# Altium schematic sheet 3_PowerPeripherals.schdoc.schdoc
size 309 x 223 mm; Symbol: Artery_A4; Device: Artery_A4; @Page Count: 4; @Create Date: 2024-01-02; @Page Name: PowerPeripherals; @Project Name: AT-START-L021; @Update Date: 2024-02-21; @Schematic Name: AT-START-L021_V1.0; @Page No: 3; Company: Artery Technology; Drawed: SD; Version: 1.0; Page Size: A4
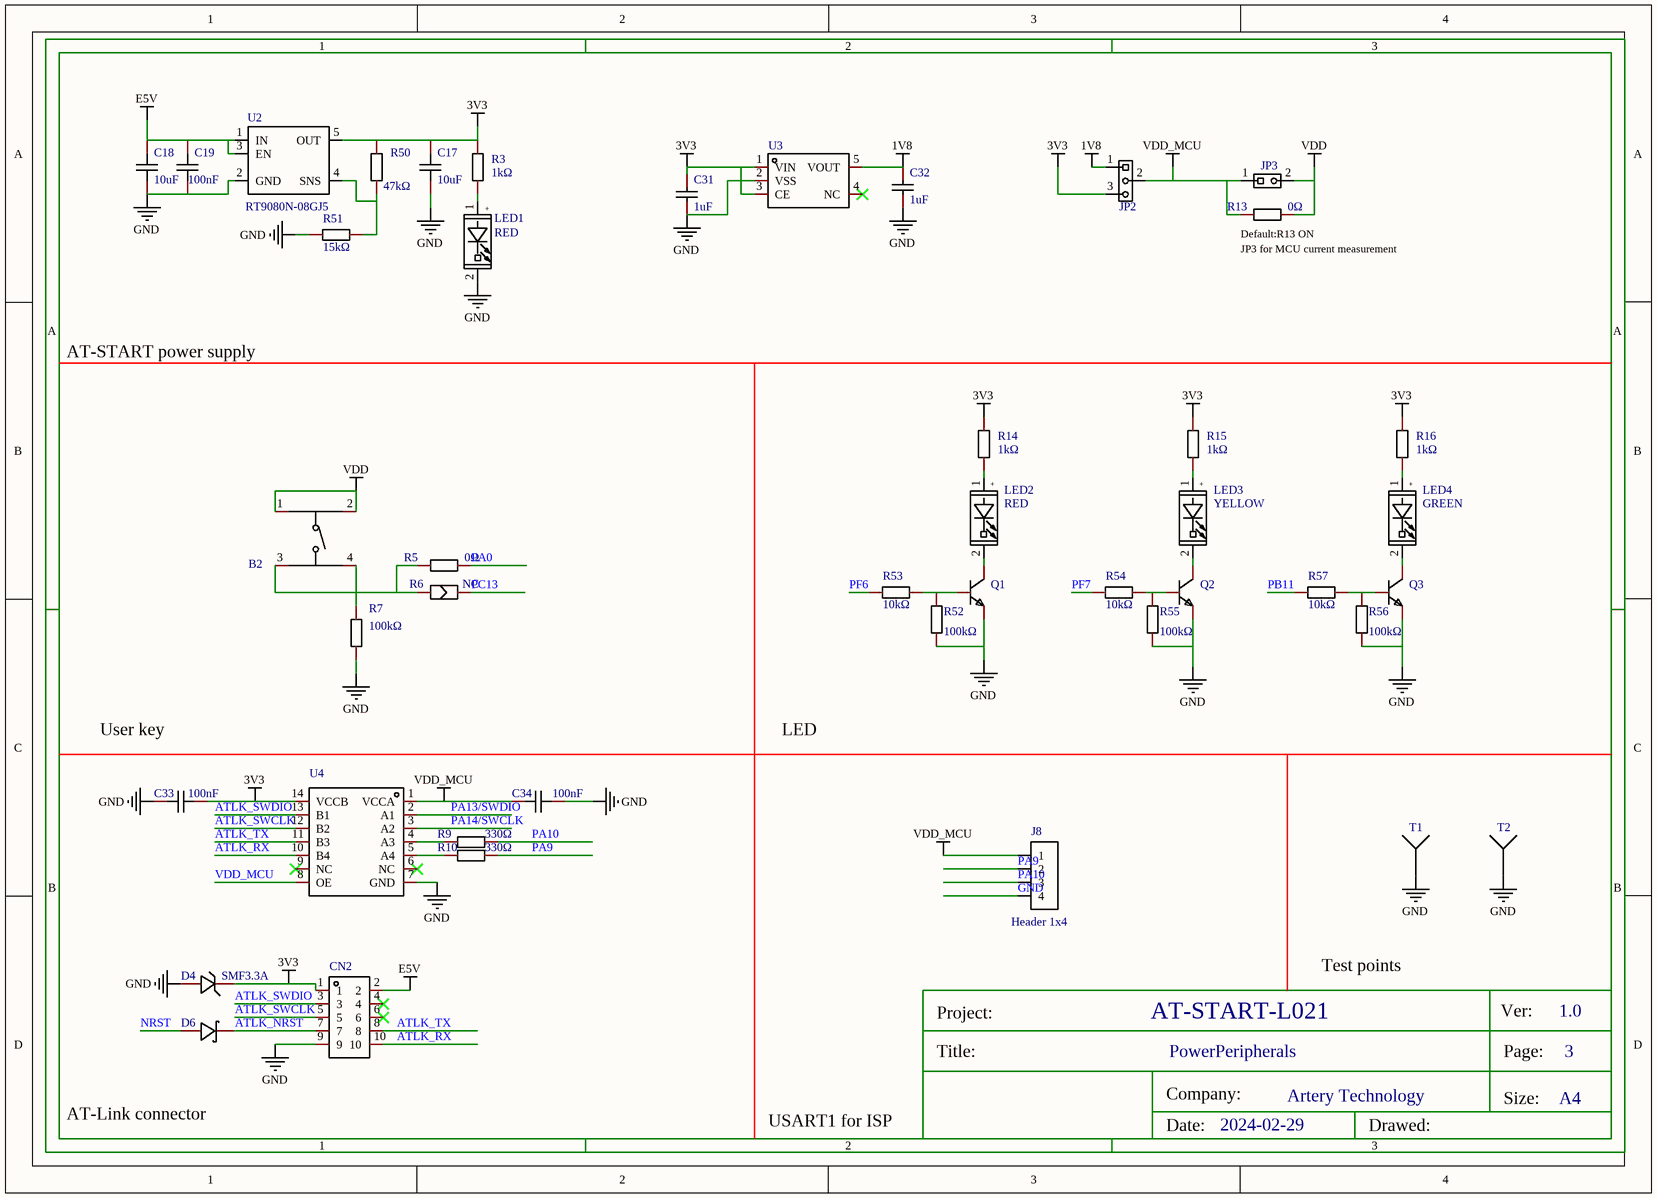
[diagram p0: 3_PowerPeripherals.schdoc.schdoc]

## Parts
B2  蓝色  [BUTTON_SMT_6*6*5]  (value not drawn)
C17  value 10uF  [C0603]  (hidden comment: CL10A106KP8NNNC)
C18  value 10uF  [C0603]  (hidden comment: CL10A106KP8NNNC)
C19  value 100nF  [C0603]  (hidden comment: CC0603KRX7R9BB104)
C31  value 1uF  [C0603]  (hidden comment: CL10A105KB8NNNC)
C32  value 1uF  [C0603]  (hidden comment: CL10A105KB8NNNC)
C33  value 100nF  [C0603]  (hidden comment: CC0603KRX7R9BB104)
C34  value 100nF  [C0603]  (hidden comment: CC0603KRX7R9BB104)
CN2  Z-21310110021001  [HDR-TH_10P-P2.54-V-M-R2-C5-S2.54]  (value not drawn)
D4  SMF3.3A  [SOD-123_L2.8-W1.8-LS3.7-RD]
D6  LRB521S-40T1G  [SOD-523_L1.2-W0.8-LS1.6-RD]  (value not drawn)
J8  Header 1x4  [HDR1X4]
JP2  Header 1x3  [HEADER 1X3]  (value not drawn)
JP3  NC(Header 1x2)  [HDR1X2]  (value not drawn)
LED1  RED  [LED0603]
LED2  RED  [LED0603]
LED3  YELLOW  [LED0603]
LED4  GREEN  [LED0603]
Q1  SS8050_C916392  [SOT-23-3_L2.9-W1.3-P1.90-LS2.4-BR]  (value not drawn)
Q2  SS8050_C916392  [SOT-23-3_L2.9-W1.3-P1.90-LS2.4-BR]  (value not drawn)
Q3  SS8050_C916392  [SOT-23-3_L2.9-W1.3-P1.90-LS2.4-BR]  (value not drawn)
R3  value 1kΩ  [R0603]  (hidden comment: 0603WAF1001T5E)
R5  value 0Ω  [R0603]  (hidden comment: 0603WAF0000T5E)
R6  NC  [SB-PAD]
R7  value 100kΩ  [R0603]  (hidden comment: 0603WAF1003T5E)
R9  330Ω  [R0603]
R10  330Ω  [R0603]
R13  value 0Ω  [R0603]  (hidden comment: 0603WAF0000T5E)
R14  value 1kΩ  [R0603]  (hidden comment: 0603WAF1001T5E)
R15  value 1kΩ  [R0603]  (hidden comment: 0603WAF1001T5E)
R16  value 1kΩ  [R0603]  (hidden comment: 0603WAF1001T5E)
R50  value 47kΩ  [R0603]  (hidden comment: 0603WAF4702T5E)
R51  value 15kΩ  [R0603]  (hidden comment: 0603WAF1502T5E)
R52  value 100kΩ  [R0603]  (hidden comment: 0603WAF1003T5E)
R53  value 10kΩ  [R0603]  (hidden comment: 0603WAF1002T5E)
R54  value 10kΩ  [R0603]  (hidden comment: 0603WAF1002T5E)
R55  value 100kΩ  [R0603]  (hidden comment: 0603WAF1003T5E)
R56  value 100kΩ  [R0603]  (hidden comment: 0603WAF1003T5E)
R57  value 10kΩ  [R0603]  (hidden comment: 0603WAF1002T5E)
T1  Testpoint  [TESTHOOK]  (value not drawn)
T2  Testpoint  [TESTHOOK]  (value not drawn)
U2  RT9080N-08GJ5  [SOT-23-5]
U3  ME6211C18M5G-N  [SOT-23-5_L3.0-W1.7-P0.95-LS2.8-BR]  (value not drawn)
U4  AIPTS0104TA14.TR  [TSSOP-14_L5.0-W4.4-P0.65-LS6.4-BL]  (value not drawn)

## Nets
1V8: C32.2 JP2.1 U3.5(VOUT)
3V3: C17.2 C31.2 C33.1 CN2.1 D4.1 JP2.3 R3.2 R14.2 R15.2 R16.2 R50.2 U2.5(OUT) U3.1(VIN) U3.3(CE) U4.14(VCCB)
E5V: C18.2 C19.2 CN2.2 U2.1(IN) U2.3(EN)
GND: C17.1 C18.1 C19.1 C31.1 C32.1 C33.2 C34.1 CN2.9 D4.2 J8.4 LED1.2(CATHODE) Q1.2(E) Q2.2(E) Q3.2(E) R7.1 R51.1 R52.1 R55.1 R56.1 T1.1 T2.1 U2.2(GND) U3.2(VSS) U4.7(GND)
VDD: B2.1 B2.2 JP3.2 R13.2
VDD_MCU: C34.2 J8.1 JP2.2 JP3.1 R13.1 U4.1(VCCA) U4.8(OE)
ATLK_NRST: CN2.7 D6.1(K)
ATLK_RX: CN2.10 U4.10(B4)
ATLK_SWCLK: CN2.5 U4.12(B2)
ATLK_SWDIO: CN2.3 U4.13(B1)
ATLK_TX: CN2.8 U4.11(B3)
NRST: D6.2(A)
PA0: R5.2
PA9: J8.2 R10.2
PA10: J8.3 R9.2
PA13/SWDIO: U4.2(A1)
PA14/SWCLK: U4.3(A2)
PB11: R57.1
PC13: R6.2
PF6: R53.1
PF7: R54.1
NetB2_3: B2.3 B2.4 R5.1 R6.1 R7.2
NetLED1_1: LED1.1(ANODE) R3.1
NetLED2_1: LED2.1(ANODE) R14.1
NetLED2_2: LED2.2(CATHODE) Q1.3(C)
NetLED3_1: LED3.1(ANODE) R15.1
NetLED3_2: LED3.2(CATHODE) Q2.3(C)
NetLED4_1: LED4.1(ANODE) R16.1
NetLED4_2: LED4.2(CATHODE) Q3.3(C)
NetQ1_1: Q1.1(B) R52.2 R53.2
NetQ2_1: Q2.1(B) R54.2 R55.2
NetQ3_1: Q3.1(B) R56.2 R57.2
NetR9_1: R9.1 U4.4(A3)
NetR10_1: R10.1 U4.5(A4)
NetR50_1: R50.1 R51.2 U2.4(SNS)

Not connected (* = marked no-connect by the designer): CN2 4* 6*; U3 4(NC)*; U4 6(NC)* 9(NC)*

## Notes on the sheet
- (near R13) JP3 for MCU current measurement
- (near R13) Default:R13 ON
- AT-START power supply
- User key
- LED
- Test points
- AT-Link connector
- USART1 for ISP
- 2024-02-29

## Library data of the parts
B2 = K2-1102SP-C4SC-04: Manufacturer: 韩国韩荣; Add into BOM: yes; Contact Current: 50mA; Voltage Rating (DC): 12V; Insulation Resistance: 100MΩ; Circuit: 单刀单掷; Actuator Style: 圆形按钮; Operating Force: 250gf@±30gf; Mechanical Life: 100000; Switch Length: 6mm; Switch Height: 5mm; Description: 触点电流:50mA;额定电压(DC):12V;绝缘电阻:100MΩ;电路结构:单刀单掷;安装方式:立贴;按钮形状:圆形按钮;带灯:-;作用力:250gf@±30gf;机械寿命:100000;工作温度:-25℃~+85℃;开关长度:6mm;开关宽度:6mm;开关高度:5mm;; Pin Type: IN
C17 C18 = CL10A106KP8NNNC: Manufacturer: SAMSUNG(三星); Add into BOM: yes; Tolerance: ±10%; Voltage Rated: 10V; Temperature Coefficient: X5R; Description: 容值:10uF;精度:±10%;额定电压:10V;温度系数:X5R;; Pin Type: IN
C19 C33 C34 = CC0603KRX7R9BB104: Manufacturer: YAGEO(国巨); Add into BOM: yes; Tolerance: ±10%; Voltage Rated: 50V; Temperature Coefficient: X7R; Description: 容值:100nF;精度:±10%;额定电压:50V;温度系数:X7R;; Pin Type: IN
C31 C32 = CL10A105KB8NNNC: Manufacturer: SAMSUNG(三星); Add into BOM: yes; Tolerance: ±10%; Voltage Rated: 50V; Temperature Coefficient: X5R; Description: 容值:1uF;精度:±10%;额定电压:50V;温度系数:X5R;; Pin Type: IN
CN2 = Z-21310110021001: Manufacturer: Nextron(台湾正凌); Add into BOM: yes; Pitch: 2.54mm; Description: 间距:2.54mm;总PIN位数:10;排数:2;插针结构:-;行距:2.54mm;安装类型:直插;圆针/方针:-;额定电流:-;额定电压:-;配合针长度:-;塑高:-;触头材质:黄铜;触头镀层:-;颜色:黑色;; Pin Type: IN
D4 = SMF3.3A: Manufacturer: DOWO; Paste Type: expand; Convert to PCB: yes
D6 = LRB521S-40T1G: Manufacturer: LRC(乐山无线电); Add into BOM: yes; Reverse Voltage (Vr): 40V; Average Rectified Current (Io): 200mA; Forward Voltage (Vf@If): 300mV; Reverse Leakage Current (Ir): 20uA; Description: 直流反向耐压(Vr):40V;平均整流电流(Io):200mA;正向压降(Vf):300mV;
J8 = Header 1x4: Convert to PCB: yes
JP2 = Header 1x3: Convert to PCB: yes
JP3 = NC(Header 1x2): Convert to PCB: yes
LED1 = RED_LED0603(1): Symbol: RED(1); Convert to PCB: yes
LED2 = RED_LED0603: Convert to PCB: yes
LED3 = YELLOW_LED0603: Convert to PCB: yes
LED4 = GREEN_LED0603: Convert to PCB: yes
Q1-Q3 = SS8050_C916392: Manufacturer: JSMSEMI(杰盛微); Manufacturer Part: SS8050; Add into BOM: yes; Description: 晶体管类型:-;集电极电流(Ic):-;集射极击穿电压(Vceo):-;功率(Pd):-;
R3 R14-R16 = 0603WAF1001T5E: 电阻类型:厚膜电阻;阻值:1kΩ;精度:±1%;功率:1/10W;温度系数:±100ppm/;最大工作电压:75V;工作温度范围:-55~+155;; Manufacturer: UNI-ROYAL(厚声); Add into BOM: yes; Tolerance: ±1%; Power(Watts): 1/10W; Overload Voltage (Max): 75V; Pin Type: IN
R5 R13 = 0603WAF0000T5E: 电阻类型:厚膜电阻;阻值:0Ω;精度:±1%;功率:1/10W;温度系数:-;最大工作电压:75V;工作温度范围:-55~+155;; Manufacturer: UNI-ROYAL(厚声); Add into BOM: yes; Tolerance: ±1%; Power(Watts): 1/10W; Overload Voltage (Max): 75V; Pin Type: IN
R6 = NC_SB-PAD: Convert to PCB: yes
R7 R52 R55 R56 = 0603WAF1003T5E: 电阻类型:厚膜电阻;阻值:100kΩ;精度:±1%;功率:1/10W;温度系数:±100ppm/;最大工作电压:75V;工作温度范围:-55~+155;; Manufacturer: UNI-ROYAL(厚声); Add into BOM: yes; Tolerance: ±1%; Power(Watts): 1/10W; Overload Voltage (Max): 75V; Pin Type: IN
R9 R10 = 0603WAF3300T5E: Manufacturer: UNI-ROYAL(厚声); Symbol: 0603WAF1000T5E; Add into BOM: yes; Tolerance: ±1%; Power(Watts): 100mW; Overload Voltage (Max): 75V; Temperature Coefficient: ±100ppm/℃; Description: 阻值:330Ω;精度:±1%;功率:100mW;温度系数:±100ppm/℃;电阻类型:厚膜电阻;
R50 = 0603WAF4702T5E: 电阻类型:厚膜电阻;阻值:47kΩ;精度:±1%;功率:1/10W;温度系数:±100ppm/;最大工作电压:75V;工作温度范围:-55~+155;; Manufacturer: UNI-ROYAL(厚声); Add into BOM: yes; Tolerance: ±1%; Power(Watts): 1/10W; Overload Voltage (Max): 75V; Pin Type: IN
R51 = 0603WAF1502T5E: 电阻类型:厚膜电阻;阻值:15kΩ;精度:±1%;功率:1/10W;温度系数:±100ppm/;最大工作电压:75V;工作温度范围:-55~+155;; Manufacturer: UNI-ROYAL(厚声); Add into BOM: yes; Tolerance: ±1%; Power(Watts): 1/10W; Overload Voltage (Max): 75V; Pin Type: IN
R53 R54 R57 = 0603WAF1002T5E: 电阻类型:厚膜电阻;阻值:10kΩ;精度:±1%;功率:1/10W;温度系数:±100ppm/;最大工作电压:75V;工作温度范围:-55~+155;; Manufacturer: UNI-ROYAL(厚声); Add into BOM: yes; Tolerance: ±1%; Power(Watts): 1/10W; Overload Voltage (Max): 75V; Pin Type: IN
T1 = Testpoint_TESTHOOK: Convert to PCB: yes
T2 = Testpoint: Convert to PCB: yes
U2 = RT9080N-08GJ5: Convert to PCB: yes
U3 = ME6211C18M5G-N: Manufacturer: MICRONE(南京微盟); Add into BOM: yes; Output Type: 固定; Output Polarity: 正; Number of Outputs: 1; Maximum Input Voltage: 6.5V; Output Voltage: 1.8V; Dropout Voltage: 400mV@(200mA); Output Current: 300mA; Power Supply Rejection Ratio (PSRR): 70dB@(1kHz); Description: 输出类型:固定;输出极性:正;最大输入电压:6.5V;输出电压:1.8V;输出电流:300mA;电源纹波抑制比(PSRR):70dB@(1kHz);; Pin Type: IN
U4 = RS0104YQ: Manufacturer: RUNIC(润石); Add into BOM: yes; Channel Type: 双向; Number of Circuits: 1; Channels per Circuit: 4; Supply Voltage (VCCA): 1.65V~5.5V; Supply Voltage (VCCB): 2.3V~5.5V; Output Type: 推挽式；开路漏极; Data Rate: 24Mbps; Description: 电路数:1;每个电路通道数:4;电压(VCCA):1.65V~5.5V;电压(VCCB):2.3V~5.5V;数据速率:24Mbps;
